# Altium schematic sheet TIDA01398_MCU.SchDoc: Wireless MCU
size 431 x 279 mm; Date: Not shown in title block; ApprovedBy: Not shown in title block; CheckedBy: Not shown in title block; Author: Not shown in title block; CompanyName: Not shown in title block; DrawnBy: Gustavo Martinez; Engineer: Not shown in title block; Organization: Not shown in title block; Address1: Not shown in title block; Address2: Not shown in title block; Address3: Not shown in title block; Address4: Not shown in title block; DocumentNumber: 1; Revision: Use project parameter SCH_Rev; SheetNumber: 3; SheetTotal: 4; PageSetup: Record=PageOptions¦CenterHorizontal=True¦CenterVertical=True¦PrintScale=1.00¦XCorrection=1.00¦YCorrection=1.00¦PrintKind=0¦BorderSize=5000000¦LeftOffset=0¦BottomOffset=0¦Orientation=2¦PaperLength=1000¦PaperWidth=1000¦Scale=100¦PaperSource=15¦PrintQuality=600¦MediaType=1¦DitherType=10¦PaperKind=Letter¦PrintScaleMode=1
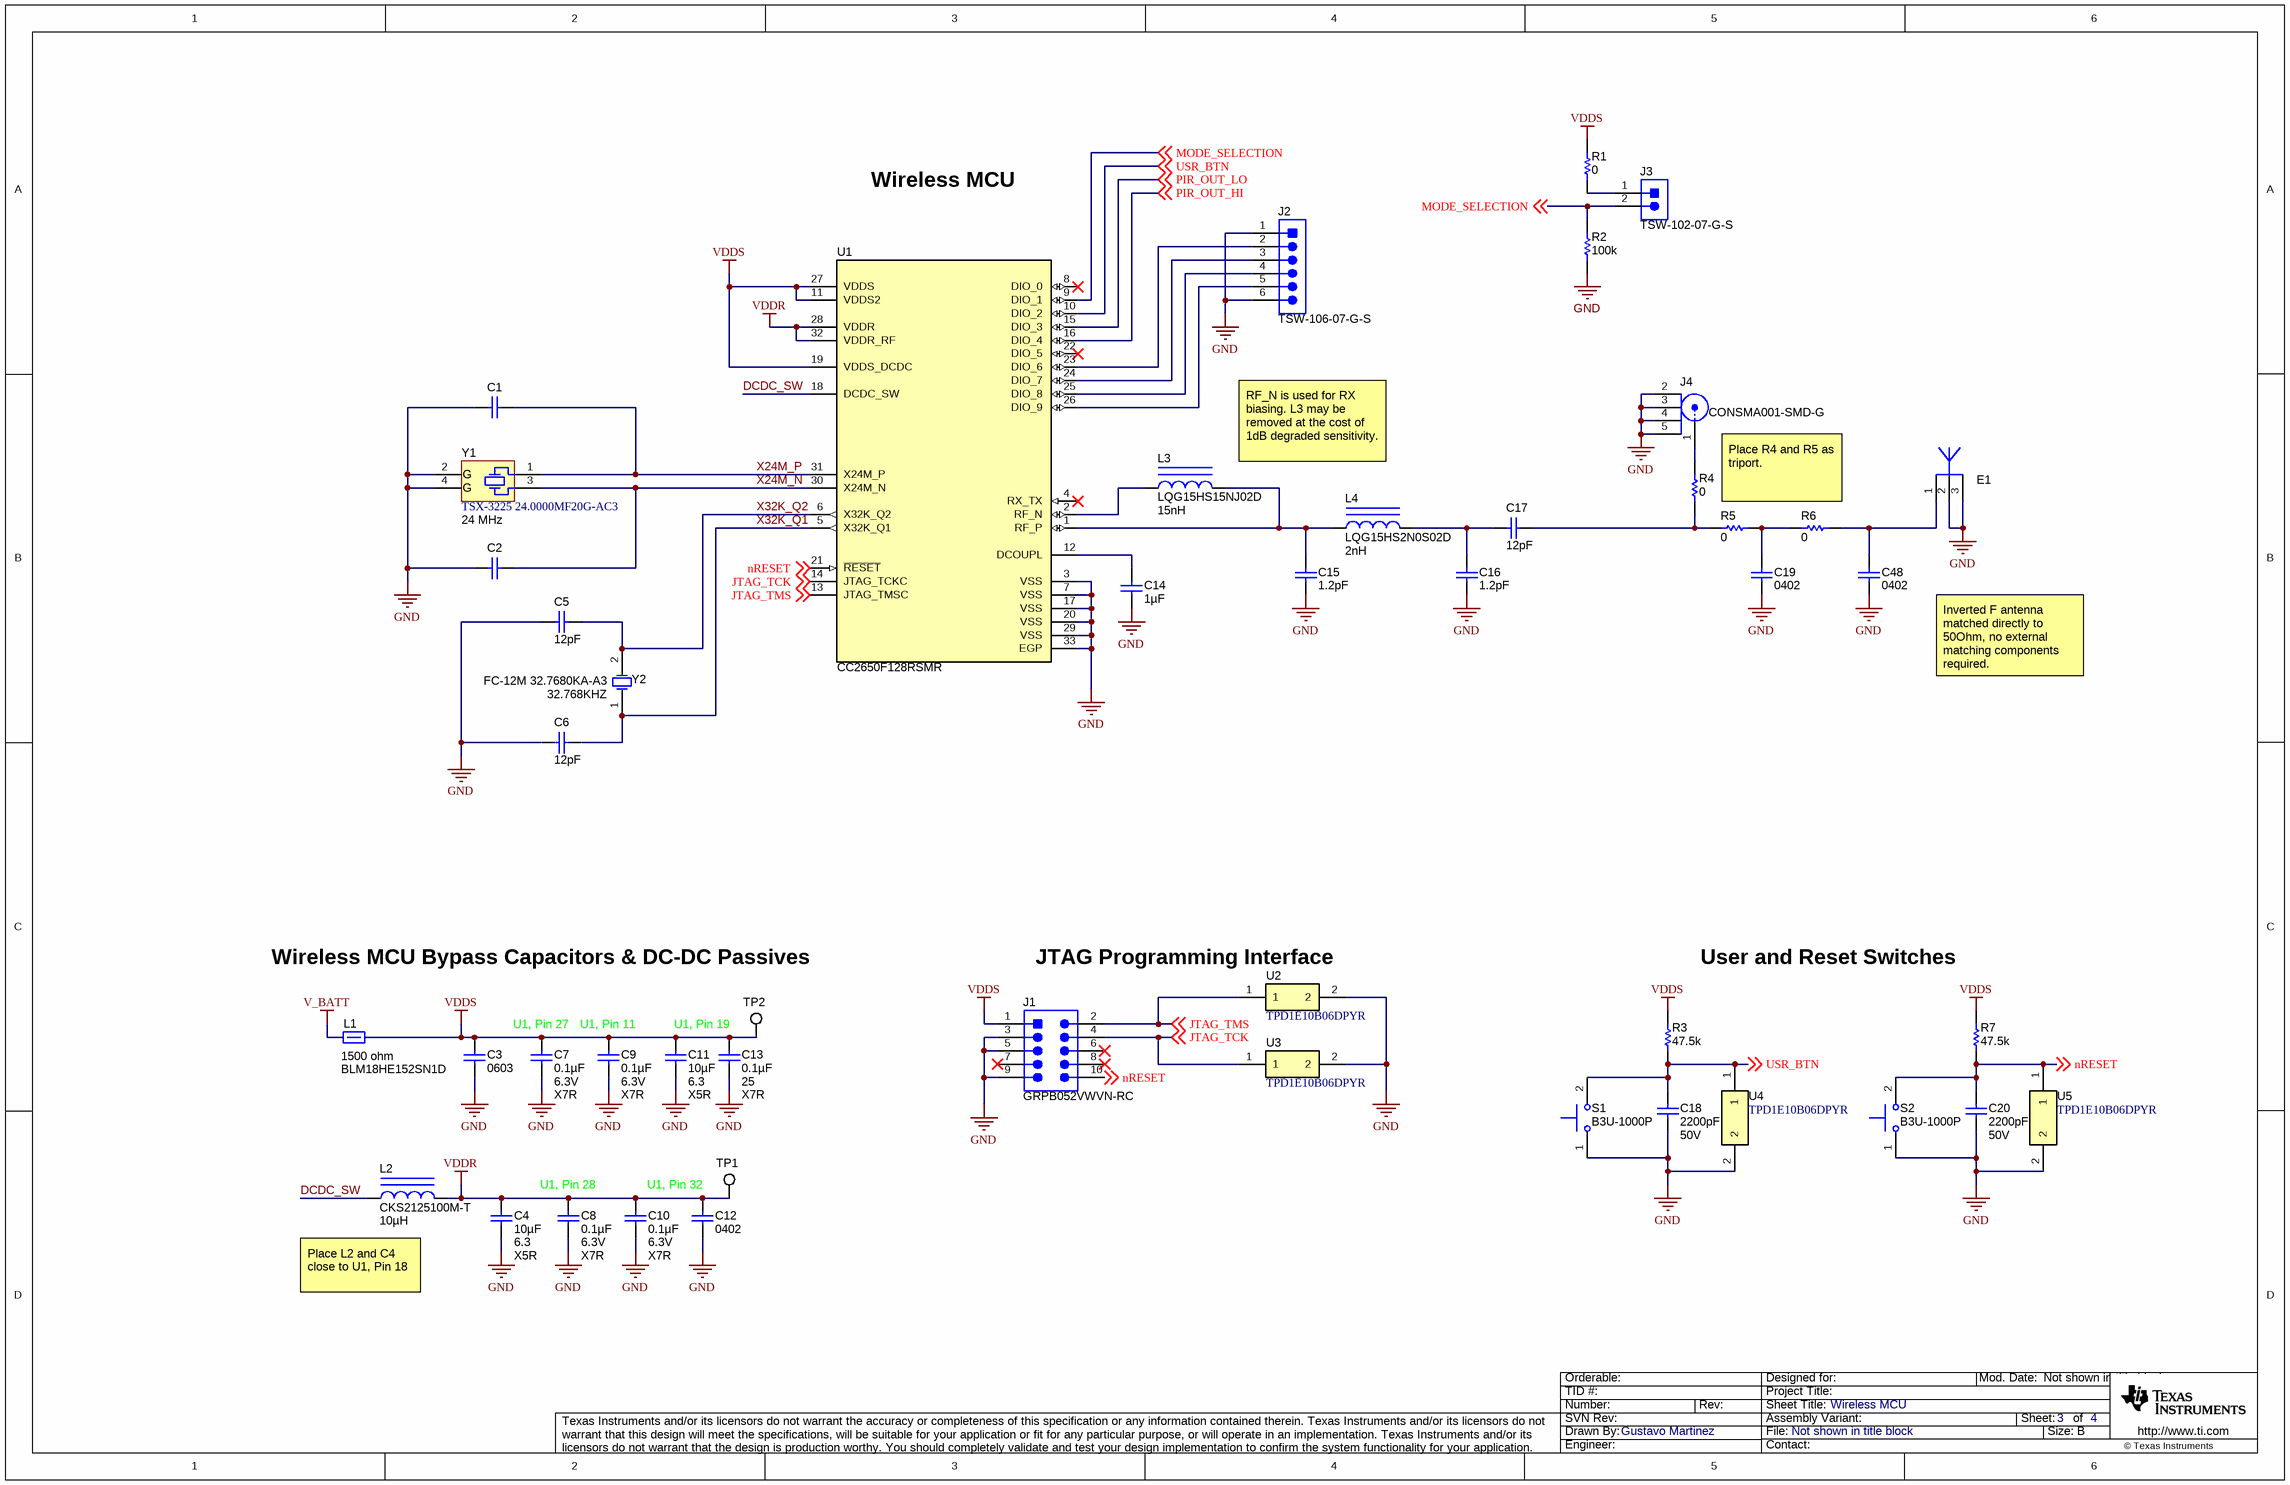
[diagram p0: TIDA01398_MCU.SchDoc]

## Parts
C1  GRM1555C1E120JA01D  [0402]  (value not drawn)
C2  GRM1555C1E120JA01D  [0402]  (value not drawn)
C3  Used in BOM report  [0603]  (value not drawn)
C4  ValueDisplayed: 10µF  VDC_V: 6.3  TempCo: X5R  [0603]  (hidden comment: GRM188R60J106ME47D)
C5  ValueDisplayed: 12pF  [0402]  (hidden comment: GRM1555C1E120JA01D)
C6  ValueDisplayed: 12pF  [0402]  (hidden comment: GRM1555C1E120JA01D)
C7  ValueDisplayed: 0.1µF  Value2: 6.3V  TempCo: X7R  [0402S]  (hidden comment: GRM155R70J104KA01D)
C8  ValueDisplayed: 0.1µF  Value2: 6.3V  TempCo: X7R  [0402S]  (hidden comment: GRM155R70J104KA01D)
C9  ValueDisplayed: 0.1µF  Value2: 6.3V  TempCo: X7R  [0402]  (hidden comment: GRM155R70J104KA01D)
C10  ValueDisplayed: 0.1µF  Value2: 6.3V  TempCo: X7R  [0402S]  (hidden comment: GRM155R70J104KA01D)
C11  ValueDisplayed: 10µF  VDC_V: 6.3  TempCo: X5R  [0603]  (hidden comment: GRM188R60J106ME47D)
C12  PackageReference: 0402  [0402S]  (hidden comment: Used in BOM report)
C13  ValueDisplayed: 0.1µF  VDC_V: 25  TempCo: X7R  [0603]  (hidden comment: GRM188R71E104KA01D)
C14  ValueDisplayed: 1µF  [0402]  (hidden comment: GRM155R61A105KE15D)
C15  ValueDisplayed: 1.2pF  [0402S]  (hidden comment: GRM1555C1H1R2BA01D)
C16  ValueDisplayed: 1.2pF  [0402S]  (hidden comment: GRM1555C1H1R2BA01D)
C17  ValueDisplayed: 12pF  [0402S]  (hidden comment: GRM1555C1H120JA01D)
C18  ValueDisplayed: 2200pF  Value2: 50V  [0402]  (hidden comment: C1005X7R1H222K)
C19  PackageReference: 0402  [0402S]  (hidden comment: Used in BOM report)
C20  ValueDisplayed: 2200pF  Value2: 50V  [0402]  (hidden comment: C1005X7R1H222K)
C48  PackageReference: 0402  [0402S]  (hidden comment: Used in BOM report)
E1  ANTENNA_DN007A  [ANTENNA_DN007A]  (value not drawn)  (net tie)
J1  GRPB052VWVN-RC  [CONN_GRPB052VWVN-RC]
J2  TSW-106-07-G-S  [TSW-106-07-G-S]
J3  TSW-102-07-G-S  [TSW-102-07-G-S]
J4  CONSMA001-SMD-G  [Linx_CONSMA001-SMD-G]
L1  value 1500 ohm  [0603]  (hidden comment: BLM18HE152SN1D)
L2  CKS2125100M-T  ValueDisplayed: 10µH  [0805_145]
L3  LQG15HS15NJ02D  ValueDisplayed: 15nH  [IND_LQG15H]
L4  LQG15HS2N0S02D  ValueDisplayed: 2nH  [IND_LQG15H]
R1  ValueDisplayed: 0  [0402]  (hidden comment: CRCW04020000Z0ED)
R2  ValueDisplayed: 100k  [0402]  (hidden comment: CRCW0402100KFKED)
R3  ValueDisplayed: 47.5k  [0402]  (hidden comment: CRCW040247K5FKED)
R4  ValueDisplayed: 0  [0402S]  (hidden comment: CRCW04020000Z0ED)
R5  ValueDisplayed: 0  [0402S]  (hidden comment: CRCW04020000Z0ED)
R6  ValueDisplayed: 0  [0402S]  (hidden comment: CRCW04020000Z0ED)
R7  ValueDisplayed: 47.5k  [0402]  (hidden comment: CRCW040247K5FKED)
S1  B3U-1000P  [SW_B3U-1000P]
S2  B3U-1000P  [SW_B3U-1000P]
TP1  5015  [Testpoint_Keystone_Miniature]  (value not drawn)
TP2  5015  [Testpoint_Keystone_Miniature]  (value not drawn)
U1  CC2650F128RSMR  [RSM0032B]
U2  TPD1E10B06DPYR  [DPY0002A]
U3  TPD1E10B06DPYR  [DPY0002A]
U4  TPD1E10B06DPYR  [DPY0002A]
U5  TPD1E10B06DPYR  [DPY0002A]
Y1  TSX-3225 24.0000MF20G-AC3  Frequency: 24 MHz  [EPSON_TSX-3225]
Y2  FC-12M 32.7680KA-A3  Frequency: 32.768KHZ  [Epson_FC-12M]

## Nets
GND: C1.1 C2.1 C3.2 C4.1 C5.2 C6.2 C7.2 C8.2 C9.2 C10.2 C11.1 C12.2 C13.1 C14.2 C15.2 C16.2 C18.1 C19.1 C20.1 C48.1 E1.2 E1.3 J1.3 J1.5 J1.9 J2.1 J2.6 J4.2 J4.3 J4.4 J4.5 R2.1 S1.1 S2.1 U1.3(VSS) U1.7(VSS) U1.17(VSS) U1.20(VSS) U1.29(VSS) U1.33(EGP) U2.2 U3.2 U4.2 U5.2 Y1.2(GND) Y1.4(GND)
V_BATT: L1.1
VDDR: C4.2 C8.1 C10.1 C12.1 L2.2 TP1.1 U1.28(VDDR) U1.32(VDDR_RF)
VDDS: C3.1 C7.1 C9.1 C11.2 C13.2 J1.1 L1.2 R1.2 R3.2 R7.2 TP2.1 U1.11(VDDS2) U1.19(VDDS_DCDC) U1.27(VDDS)
DCDC_SW: L2.1 U1.18(DCDC_SW)
JTAG_TCK: J1.4 U1.14(JTAG_TCKC) U3.1 ; off-sheet JTAG_TCK
JTAG_TMS: J1.2 U1.13(JTAG_TMSC) U2.1 ; off-sheet JTAG_TMS
MODE_SELECTION: J3.2 R2.2 U1.9(DIO_1) ; off-sheet MODE_SELECTION
nRESET: C20.2 J1.10 R7.1 S2.2 U1.21(~{RESET}) U5.1 ; off-sheet nRESET
PIR_OUT_HI: U1.16(DIO_4) ; off-sheet PIR_OUT_HI
PIR_OUT_LO: U1.15(DIO_3) ; off-sheet PIR_OUT_LO
USR_BTN: C18.2 R3.1 S1.2 U1.10(DIO_2) U4.1 ; off-sheet USR_BTN
X24M_N: C2.2 U1.30(X24M_N) Y1.3
X24M_P: C1.2 U1.31(X24M_P) Y1.1
X32K_Q1: C6.1 U1.5(X32K_Q1) Y2.1(OSC1)
X32K_Q2: C5.1 U1.6(X32K_Q2) Y2.2(OSC2)
NetC14_1: C14.1 U1.12(DCOUPL)
NetC15_1: C15.1 L3.2 L4.1 U1.1(RF_P)
NetC16_1: C16.1 C17.2 L4.2
NetC17_1: C17.1 R4.1 R5.1
NetC19_2: C19.2 R5.2 R6.1
NetC48_2: C48.2 E1.1 R6.2
NetJ2_2: J2.2 U1.23(DIO_6)
NetJ2_3: J2.3 U1.24(DIO_7)
NetJ2_4: J2.4 U1.25(DIO_8)
NetJ2_5: J2.5 U1.26(DIO_9)
NetJ3_1: J3.1 R1.1
NetJ4_1: J4.1 R4.2
NetL3_1: L3.1 U1.2(RF_N)

Not connected (* = marked no-connect by the designer): J1 6* 7* 8*; U1 4(RX_TX)* 8(DIO_0)* 22(DIO_5)*

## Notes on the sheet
- Wireless MCU
- (near L3) RF_N is used for RX biasing. L3 may be removed at the cost of 1dB degraded sensitivity.
- Place R4 and R5 as triport.
- Inverted F antenna matched directly to 50Ohm, no external matching components required.
- Wireless MCU Bypass Capacitors & DC-DC Passives
- (near U2) JTAG Programming Interface
- User and Reset Switches
- (near C7) U1, Pin 27
- (near C9) U1, Pin 11
- U1, Pin 19
- (near C8) U1, Pin 28
- U1, Pin 32
- (near L2) Place L2 and C4 close to U1, Pin 18

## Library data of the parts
C1 C2 C5 C6 = GRM1555C1E120JA01D: CAP, CERM, 12 pF, 25 V, +/- 5%, C0G/NP0, 0402; Manufacturer: MuRata; Polarized: N; CompType: Capacitor; Value: 12pF; U/M: EA; Cap_F: 0.000000000012; Tolerance_%: 5; Value1: Unknown; VDC_V: 25; Value2: 25V; TaMin_C: -55; TaMax_C: 125; AEC Category: Q200
C3 C12 C19 C48 = Capacitor: CAP, CERM, xxxF, xxV, [TempCo], xx%, [PackageReference]; Polarized: N; U/M: EA
C4 C11 = GRM188R60J106ME47D: CAP, CERM, 10 µF, 6.3 V, +/- 20%, X5R, 0603; Manufacturer: MuRata; Polarized: N; CompType: Capacitor; Value: 10uF; U/M: EA; Cap_F: 0.00001; Tolerance_%: 20; ESR_ohm: 0.009; Value1: 0.009 ohm; Value2: 6.3V; IRMS_A: 2.74; TaMin_C: -55; TaMax_C: 125; AEC Category: Q200
C7 C8 C10 = GRM155R70J104KA01D: CAP, CERM, 0.1 µF, 6.3 V, +/- 10%, X7R, 0402; Manufacturer: MuRata; Polarized: N; CompType: Capacitor; Value: 0.1uF; U/M: EA; Cap_F: 0.0000001; Tolerance_%: 10; Value1: Unknown; VDC_V: 6.3; TaMin_C: -55; TaMax_C: 125; Cap_Case: 0402
C9 = GRM155R70J104KA01D: CAP, CERM, 0.1 µF, 6.3 V, +/- 10%, X7R, 0402; Manufacturer: MuRata; Polarized: N; CompType: Capacitor; Value: 0.1uF; U/M: EA; Cap_F: 0.0000001; Tolerance_%: 10; Value1: Unknown; VDC_V: 6.3; TaMin_C: -55; TaMax_C: 125
C13 = GRM188R71E104KA01D: CAP, CERM, 0.1 µF, 25 V, +/- 10%, X7R, 0603; Manufacturer: MuRata; Polarized: N; CompType: Capacitor; Value: 0.1uF; U/M: EA; Cap_F: 0.0000001; Tolerance_%: 10; Value1: Unknown; Value2: 25V; TaMin_C: -55; TaMax_C: 125; AEC Category: Q200
C14 = GRM155R61A105KE15D: CAP, CERM, 1 µF, 10 V, +/- 10%, X5R, 0402; Manufacturer: MuRata; Polarized: N; CompType: Capacitor; Value: 1uF; U/M: EA; Cap_F: 0.000001; Tolerance_%: 10; Value1: Unknown; Value2: 10V; TaMin_C: -55; TaMax_C: 85; AEC Category: Q200
C15 C16 = GRM1555C1H1R2BA01D: CAP, CERM, 1.2 pF, 50 V, +/- 8.3%, C0G/NP0, 0402; Manufacturer: MuRata; Polarized: N; CompType: Capacitor; Value: 1.2pF; U/M: EA; Cap_F: 0.0000000000012; Tolerance_%: 8.3; Value1: Unknown; VDC_V: 50; Value2: 50V; TaMin_C: -55; TaMax_C: 125; Cap_Case: 0402; AEC Category: Q200
C17 = GRM1555C1H120JA01D: CAP, CERM, 12 pF, 50 V, +/- 5%, C0G/NP0, 0402; Manufacturer: MuRata; Polarized: N; CompType: Capacitor; Value: 12pF; U/M: EA; Cap_F: 0.000000000012; Tolerance_%: 5; Value1: Unknown; VDC_V: 50; Value2: 50V; TaMin_C: -55; TaMax_C: 125; Cap_Case: 0402; AEC Category: Q200
C18 C20 = C1005X7R1H222K: CAP, CERM, 2200 pF, 50 V, +/- 10%, X7R, 0402; Manufacturer: TDK; Polarized: N; CompType: Capacitor; Value: 2200pF; U/M: EA; Cap_F: 0.0000000022; Tolerance_%: 10; ESR_ohm: 0.1433; Value1: 0.1433 ohm; VDC_V: 50; TaMin_C: -55; TaMax_C: 125; AEC Category: Q200
E1 = ANTENNA_DN007A: 2.4GHz PCB Antenna.  There is nothing to buy or mount.; SymbolCreator: a0412235
J1 = GRPB052VWVN-RC: Header, 50mil, 5x2, Gold, TH; Manufacturer: Sullins Connector Solutions; SymbolCreator: a0412235; U/M: EA
J2 = TSW-106-07-G-S: Header, 100mil, 6x1, Gold, TH; Manufacturer: Samtec; SymbolCreator: a0412235; U/M: EA
J3 = TSW-102-07-G-S: Header, 100mil, 2x1, Gold, TH; Manufacturer: Samtec; SymbolCreator: a0412235; U/M: EA
J4 = CONSMA001-SMD-G: Jack, SMA, PCB, Gold, SMT; Manufacturer: Linx Technologies; SymbolCreator: X0208326; U/M: EA
L1 = BLM18HE152SN1D: Ferrite Bead, 1500 ohm @ 100 MHz, 0.5 A, 0603; Manufacturer: MuRata; Imax_A: 0.5; Value1: 0.5 ohm; Value2: 0.5A; ZTyp@100MHz_Ohm: 1500
L2 = CKS2125100M-T: Inductor, Multilayer, Ferrite, 10uH, 0.11A, 0.52 ohm, SMD; Manufacturer: Taiyo Yuden; Ind_H: 10.0E-6; Imax_A: 0.11; DCR_ohm: 0.52
L3 = LQG15HS15NJ02D: Inductor, Multilayer, Air Core, 15 nH, 0.3 A, 0.32 ohm, SMD; Manufacturer: MuRata; Value: 15nH; Ind_H: 15.0E-9; Imax_A: 0.3; Irms: 0.3A @ C rise; Isat: 0.3A @ % inductance drop; DCR_ohm: 0.32; Value2: 0.3A; AEC Category: Q200
L4 = LQG15HS2N0S02D: Inductor, Multilayer, Air Core, 2 nH, 0.3 A, 0.1 ohm, SMD; Manufacturer: MuRata; Value: 2nH; Ind_H: 2.0E-9; Imax_A: 0.3; Irms: 0.3A @ C rise; Isat: 0.3A @ % inductance drop; DCR_ohm: 0.1; Value1: 0.1 ohm; Value2: 0.3A; AEC Category: Q200
R1 R4-R6 = CRCW04020000Z0ED: RES, 0, 5%, 0.063 W, 0402; Manufacturer: Vishay-Dale; CompType: Resistor; Value: 0; Value_Code: 0000; Tolerance_%: 5; Power_W: 0.063; Value2: 0.063W; VDC_V: 50; TempCo: 200 ppm/C; EIA_Code: E24; U/M: EA; AEC Category: Q200
R2 = CRCW0402100KFKED: RES, 100 k, 1%, 0.063 W, 0402; Manufacturer: Vishay-Dale; CompType: Resistor; Value: 100k; Res_ohm: 100000; Tolerance_%: 1; Power_W: 0.063; Value2: 0.063W; VDC_V: 50; TempCo: 100 ppm/C; EIA_Code: E96; U/M: EA; AEC Category: Q200
R3 R7 = CRCW040247K5FKED: RES, 47.5 k, 1%, 0.063 W, 0402; Manufacturer: Vishay-Dale; CompType: Resistor; Res_ohm: 47500; Value: 47.5k; Value_Code: 47k5; Tolerance_%: 1; Power_W: 0.063; Value2: 0.063W; VDC_V: 50; TempCo: 100 ppm/C; EIA_Code: E96; U/M: EA; AEC Category: Q200
S1 S2 = B3U-1000P: SWITCH TACTILE SPST-NO 0.05A 12V; Manufacturer: Omron Electronic Components; SymbolCreator: a0412235; VDC_V: 12; SwitchFunction: Off-Mom; PositionCount: 1; CurrentRating_mA: 50
TP1 TP2 = 5015: Test Point, Miniature, SMT; Manufacturer: Keystone; CompType: Test Point Loop; U/M: EA
U1 = CC2650F128RSMR: Ultra low-power ARM Cortex M3 2.4 GHz Radio MCU, RSM0032B; Alternate PartNumber: CC2650F128RSMT; Manufacturer: Texas Instruments; SymbolCreator: Altium; CompType: IC; U/M: EA
U2-U5 = TPD1E10B06DPYR: ESD in 0402 Package with 10 pF Capacitance and 6 V Breakdown, 1 Channel, -40 to +125 degC, 2-pin X2SON (DPY), Green (RoHS & no Sb/Br); Manufacturer: Texas Instruments; Alternate PartNumber: Equivalent; Breakdown Voltage(Min)(V): 6; Eco-Plan: TBD; IEC 61000-4-2 Air-Gap(+/- kV): 30; IO Capacitance(Typ)(pF): 10; SubFamily: ESD Solution
Y1 = TSX-3225 24.0000MF20G-AC3: Crystal, 24 MHz, 9 pF, SMD; Manufacturer: Epson; SymbolCreator: a0412235; U/M: EA; TaMin_C: -40; TaMax_C: 85; Frequency Stability: ±20ppm
Y2 = FC-12M 32.7680KA-A3: Crystal, 32.768kHz, 12.5pF, SMD; Manufacturer: Epson; SymbolCreator: a0412235; U/M: EA; TaMin_C: -40; TaMax_C: 85; Frequency Stability: ±20ppm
